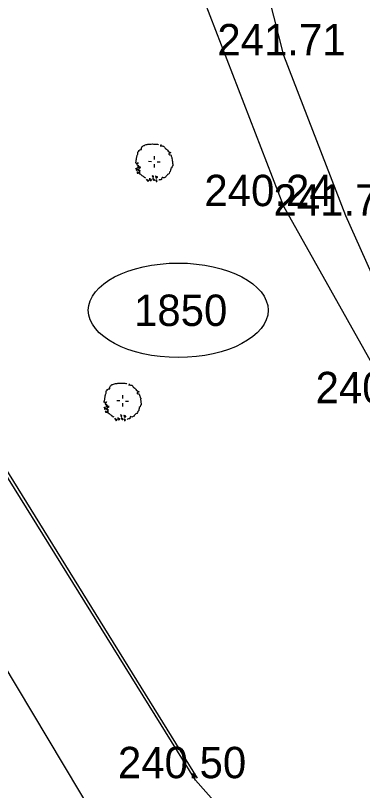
# Model space of a CAD drawing. Extents: x -601739 to -601440, y -1201912 to -1200862.
# Drawn here: x -601531.2 to -601509.07, y -1201685.45 to -1201636.06 of the extents above; entities that cross this region are included whole.
import ezdxf

# ---------------------------------------------------------------- set-up
doc = ezdxf.new("R2010")
doc.units = 0
for name, color, linetype in [('Hranice parcel', 7, 'Continuous'), ('Parcelní čísla', 7, 'Continuous'), ('u_dotčené parcely', 7, 'Continuous'), ('u_hrany', 7, 'Continuous'), ('u_vysadba', 7, 'Continuous'), ('u_vyska', 7, 'Continuous')]:
    doc.layers.add(name, color=color, linetype=linetype)

msp = doc.modelspace()

# ---------------------------------------------------------------- linework, layer by layer
at = {"layer": 'Hranice parcel'}
for points in [[(-601445.87, -1201723.83), (-601456.99, -1201723.59), (-601475.22, -1201720.69), (-601492.39, -1201715.61), (-601519.73, -1201684.8), (-601540.64, -1201651.14), (-601563.05, -1201608.38), (-601567.44, -1201599.25)], [(-601574.75, -1201602.78), (-601570.23, -1201611.8), (-601545.97, -1201654.03), (-601525.15, -1201688.8), (-601494.52, -1201722.78), (-601477.14, -1201727.24), (-601477.125, -1201727.243)]]:
    msp.add_lwpolyline(points, dxfattribs=at)
at = {"layer": 'u_dotčené parcely'}
msp.add_ellipse((-601520.821, -1201654.846), major_axis=(-5.732, 0), ratio=0.524694, dxfattribs=at)
at = {"layer": 'u_hrany'}
for points in [[(-601514.2, -1201569.51), (-601517.03, -1201570.93), (-601522.49, -1201584.67), (-601523.6, -1201596.8), (-601523.78, -1201607.28), (-601522.35, -1201622.38), (-601520.26, -1201632.29), (-601514.11, -1201648.21), (-601507.05, -1201660.77), (-601502.96, -1201664.86), (-601510.13, -1201648.82), (-601514.08, -1201638.6), (-601517, -1201627.14), (-601517.98, -1201618.06), (-601518.55, -1201594.5), (-601514.93, -1201583.59), (-601509.76, -1201580.82)], [(-601567.51, -1201596.21), (-601562.55, -1201607.8), (-601549.33, -1201634.79), (-601540.29, -1201651.32), (-601519.62, -1201684.67)]]:
    msp.add_lwpolyline(points, dxfattribs=at)
at = {"layer": 'u_vysadba'}
for points in [[(-601523.335, -1201644.685), (-601523.333, -1201644.656), (-601523.273, -1201644.63), (-601523.243, -1201644.617), (-601523.213, -1201644.604), (-601523.184, -1201644.605), (-601523.155, -1201644.607), (-601523.168, -1201644.577), (-601523.181, -1201644.547), (-601523.164, -1201644.504), (-601523.147, -1201644.461), (-601523.116, -1201644.418), (-601523.085, -1201644.391), (-601523.054, -1201644.363), (-601523.009, -1201644.336), (-601522.965, -1201644.338), (-601522.934, -1201644.311), (-601522.86, -1201644.285), (-601522.801, -1201644.274), (-601522.756, -1201644.262), (-601522.698, -1201644.265), (-601522.653, -1201644.252), (-601522.609, -1201644.255), (-601522.536, -1201644.259), (-601522.463, -1201644.248), (-601522.39, -1201644.252), (-601522.302, -1201644.256), (-601522.214, -1201644.261), (-601522.141, -1201644.265), (-601522.098, -1201644.282), (-601522.07, -1201644.298)], [(-601521.923, -1201644.291), (-601521.939, -1201644.319), (-601521.941, -1201644.349), (-601521.957, -1201644.377), (-601521.912, -1201644.365), (-601521.883, -1201644.366), (-601521.854, -1201644.368), (-601521.811, -1201644.385), (-601521.767, -1201644.387), (-601521.725, -1201644.419), (-601521.697, -1201644.449), (-601521.67, -1201644.495), (-601521.628, -1201644.526), (-601521.572, -1201644.573), (-601521.53, -1201644.619), (-601521.503, -1201644.65), (-601521.462, -1201644.711), (-601521.405, -1201644.743), (-601521.363, -1201644.775), (-601521.32, -1201644.791), (-601521.321, -1201644.821)], [(-601523.335, -1201644.685), (-601523.336, -1201644.7), (-601523.382, -1201644.741), (-601523.413, -1201644.769), (-601523.415, -1201644.813), (-601523.417, -1201644.856), (-601523.42, -1201644.915), (-601523.437, -1201644.958), (-601523.453, -1201644.986), (-601523.469, -1201645.015), (-601523.487, -1201645.072), (-601523.489, -1201645.102), (-601523.492, -1201645.16), (-601523.494, -1201645.204), (-601523.496, -1201645.233), (-601523.514, -1201645.305), (-601523.531, -1201645.348), (-601523.533, -1201645.392), (-601523.549, -1201645.42), (-601523.536, -1201645.45), (-601523.493, -1201645.467), (-601523.404, -1201645.443), (-601523.374, -1201645.43), (-601523.407, -1201645.487), (-601523.437, -1201645.514), (-601523.453, -1201645.543), (-601523.456, -1201645.586), (-601523.427, -1201645.588), (-601523.383, -1201645.59), (-601523.37, -1201645.62), (-601523.387, -1201645.663), (-601523.403, -1201645.692), (-601523.405, -1201645.736), (-601523.407, -1201645.779)], [(-601521.321, -1201644.821), (-601521.366, -1201644.833), (-601521.411, -1201644.845), (-601521.427, -1201644.874), (-601521.414, -1201644.904), (-601521.387, -1201644.949), (-601521.357, -1201644.936), (-601521.312, -1201644.924), (-601521.284, -1201644.954), (-601521.271, -1201644.984), (-601521.273, -1201645.014), (-601521.247, -1201645.074), (-601521.235, -1201645.118), (-601521.222, -1201645.163), (-601521.195, -1201645.208), (-601521.197, -1201645.237), (-601521.199, -1201645.281), (-601521.201, -1201645.31), (-601521.189, -1201645.355), (-601521.177, -1201645.414), (-601521.18, -1201645.472), (-601521.169, -1201645.532), (-601521.17, -1201645.561), (-601521.172, -1201645.59), (-601521.174, -1201645.634), (-601521.205, -1201645.661), (-601521.206, -1201645.691), (-601521.223, -1201645.734), (-601521.239, -1201645.762), (-601521.285, -1201645.804), (-601521.289, -1201645.862), (-601521.306, -1201645.92), (-601521.325, -1201645.992), (-601521.372, -1201646.048), (-601521.405, -1201646.119), (-601521.437, -1201646.176), (-601521.497, -1201646.202), (-601521.528, -1201646.23), (-601521.574, -1201646.272), (-601521.605, -1201646.314), (-601521.622, -1201646.357), (-601521.682, -1201646.383), (-601521.727, -1201646.395), (-601521.757, -1201646.408), (-601521.8, -1201646.391), (-601521.843, -1201646.375), (-601521.86, -1201646.418), (-601521.877, -1201646.475), (-601521.894, -1201646.518), (-601521.939, -1201646.531), (-601521.983, -1201646.528)], [(-601522.335, -1201645.227), (-601522.325, -1201645.022)], [(-601523.539, -1201645.772), (-601523.526, -1201645.802), (-601523.513, -1201645.847), (-601523.5, -1201645.877), (-601523.502, -1201645.906), (-601523.473, -1201645.922), (-601523.443, -1201645.895), (-601523.397, -1201645.853), (-601523.426, -1201645.852), (-601523.468, -1201645.82), (-601523.511, -1201645.803)], [(-601523.357, -1201645.65), (-601523.359, -1201645.694), (-601523.346, -1201645.724), (-601523.334, -1201645.769), (-601523.32, -1201645.799), (-601523.291, -1201645.8), (-601523.275, -1201645.772), (-601523.215, -1201645.746), (-601523.258, -1201645.729), (-601523.287, -1201645.713), (-601523.344, -1201645.68)], [(-601522.519, -1201645.378), (-601522.724, -1201645.367)], [(-601522.352, -1201645.533), (-601522.362, -1201645.738)], [(-601522.169, -1201645.396), (-601521.963, -1201645.393)], [(-601523.449, -1201646.011), (-601523.439, -1201646.1), (-601523.395, -1201646.102), (-601523.366, -1201646.104), (-601523.321, -1201646.091), (-601523.379, -1201646.074), (-601523.423, -1201646.071), (-601523.436, -1201646.041)], [(-601523.381, -1201645.839), (-601523.34, -1201645.885), (-601523.298, -1201645.932), (-601523.256, -1201645.963)], [(-601523.256, -1201645.963), (-601523.285, -1201645.962), (-601523.314, -1201645.96), (-601523.344, -1201645.958), (-601523.357, -1201645.929), (-601523.355, -1201645.899), (-601523.368, -1201645.869)], [(-601522.885, -1201646.422), (-601522.928, -1201646.405), (-601522.956, -1201646.389), (-601522.986, -1201646.387), (-601523.012, -1201646.342), (-601523.041, -1201646.326), (-601523.083, -1201646.294), (-601523.126, -1201646.277), (-601523.168, -1201646.231), (-601523.195, -1201646.201), (-601523.267, -1201646.168), (-601523.264, -1201646.124), (-601523.262, -1201646.08), (-601523.275, -1201646.05), (-601523.304, -1201646.034), (-601523.272, -1201645.992), (-601523.243, -1201645.993)], [(-601522.481, -1201646.253), (-601522.47, -1201646.327), (-601522.443, -1201646.372), (-601522.398, -1201646.36), (-601522.397, -1201646.331), (-601522.395, -1201646.301), (-601522.438, -1201646.285), (-601522.467, -1201646.268)], [(-601522.278, -1201646.293), (-601522.252, -1201646.353), (-601522.239, -1201646.398), (-601522.212, -1201646.428), (-601522.182, -1201646.415), (-601522.15, -1201646.373), (-601522.149, -1201646.344), (-601522.192, -1201646.341), (-601522.221, -1201646.325), (-601522.249, -1201646.309), (-601522.278, -1201646.308)], [(-601522.873, -1201646.481), (-601522.777, -1201646.603), (-601522.75, -1201646.649), (-601522.719, -1201646.606), (-601522.717, -1201646.577), (-601522.746, -1201646.561), (-601522.789, -1201646.544), (-601522.817, -1201646.528), (-601522.846, -1201646.512)], [(-601522.651, -1201646.434), (-601522.655, -1201646.507), (-601522.643, -1201646.552), (-601522.615, -1201646.583), (-601522.556, -1201646.571), (-601522.525, -1201646.543), (-601522.538, -1201646.514), (-601522.581, -1201646.497), (-601522.624, -1201646.48)], [(-601522.446, -1201646.431), (-601522.362, -1201646.508), (-601522.334, -1201646.524), (-601522.321, -1201646.554), (-601522.352, -1201646.582), (-601522.381, -1201646.58), (-601522.394, -1201646.55), (-601522.421, -1201646.505), (-601522.448, -1201646.474)], [(-601522.247, -1201646.544), (-601522.236, -1201646.617), (-601522.223, -1201646.647), (-601522.193, -1201646.634), (-601522.162, -1201646.592), (-601522.189, -1201646.561), (-601522.218, -1201646.545), (-601522.247, -1201646.544)], [(-601521.983, -1201646.528), (-601522.027, -1201646.541), (-601522.058, -1201646.568)], [(-601525.353, -1201659.926), (-601525.352, -1201659.897), (-601525.292, -1201659.871), (-601525.262, -1201659.858), (-601525.232, -1201659.845), (-601525.203, -1201659.847), (-601525.173, -1201659.848), (-601525.186, -1201659.818), (-601525.199, -1201659.788), (-601525.183, -1201659.745), (-601525.166, -1201659.702), (-601525.134, -1201659.66), (-601525.103, -1201659.632), (-601525.073, -1201659.605), (-601525.027, -1201659.578), (-601524.983, -1201659.58), (-601524.953, -1201659.552), (-601524.878, -1201659.527), (-601524.819, -1201659.515), (-601524.774, -1201659.503), (-601524.716, -1201659.506), (-601524.671, -1201659.494), (-601524.628, -1201659.496), (-601524.555, -1201659.5), (-601524.481, -1201659.489), (-601524.408, -1201659.493), (-601524.32, -1201659.498), (-601524.233, -1201659.502), (-601524.16, -1201659.506), (-601524.117, -1201659.523), (-601524.088, -1201659.539)], [(-601523.941, -1201659.532), (-601523.957, -1201659.561), (-601523.959, -1201659.59), (-601523.975, -1201659.619), (-601523.931, -1201659.606), (-601523.901, -1201659.608), (-601523.872, -1201659.609), (-601523.829, -1201659.626), (-601523.785, -1201659.629), (-601523.743, -1201659.66), (-601523.715, -1201659.691), (-601523.688, -1201659.736), (-601523.646, -1201659.768), (-601523.59, -1201659.815), (-601523.549, -1201659.861), (-601523.521, -1201659.891), (-601523.48, -1201659.952), (-601523.423, -1201659.984), (-601523.381, -1201660.016), (-601523.338, -1201660.033), (-601523.34, -1201660.062)], [(-601525.353, -1201659.926), (-601525.354, -1201659.941), (-601525.4, -1201659.983), (-601525.431, -1201660.01), (-601525.433, -1201660.054), (-601525.435, -1201660.098), (-601525.439, -1201660.156), (-601525.455, -1201660.199), (-601525.472, -1201660.228), (-601525.488, -1201660.256), (-601525.505, -1201660.314), (-601525.507, -1201660.343), (-601525.51, -1201660.401), (-601525.512, -1201660.445), (-601525.514, -1201660.474), (-601525.532, -1201660.547), (-601525.549, -1201660.59), (-601525.552, -1201660.633), (-601525.568, -1201660.662), (-601525.555, -1201660.692), (-601525.512, -1201660.709), (-601525.422, -1201660.684), (-601525.393, -1201660.671), (-601525.425, -1201660.728), (-601525.456, -1201660.756), (-601525.472, -1201660.784), (-601525.474, -1201660.828), (-601525.445, -1201660.829), (-601525.401, -1201660.832), (-601525.388, -1201660.862), (-601525.405, -1201660.905), (-601525.421, -1201660.933), (-601525.423, -1201660.977), (-601525.426, -1201661.021)], [(-601523.34, -1201660.062), (-601523.384, -1201660.074), (-601523.429, -1201660.087), (-601523.445, -1201660.115), (-601523.432, -1201660.145), (-601523.405, -1201660.19), (-601523.375, -1201660.177), (-601523.33, -1201660.165), (-601523.303, -1201660.196), (-601523.29, -1201660.226), (-601523.291, -1201660.255), (-601523.265, -1201660.315), (-601523.253, -1201660.36), (-601523.241, -1201660.404), (-601523.214, -1201660.449), (-601523.215, -1201660.479), (-601523.218, -1201660.522), (-601523.219, -1201660.552), (-601523.207, -1201660.596), (-601523.195, -1201660.655), (-601523.198, -1201660.714), (-601523.187, -1201660.773), (-601523.188, -1201660.802), (-601523.19, -1201660.831), (-601523.192, -1201660.875), (-601523.223, -1201660.903), (-601523.225, -1201660.932), (-601523.241, -1201660.975), (-601523.258, -1201661.004), (-601523.304, -1201661.045), (-601523.307, -1201661.103), (-601523.324, -1201661.161), (-601523.343, -1201661.233), (-601523.39, -1201661.289), (-601523.423, -1201661.361), (-601523.455, -1201661.418), (-601523.515, -1201661.444), (-601523.546, -1201661.472), (-601523.592, -1201661.513), (-601523.624, -1201661.555), (-601523.64, -1201661.598), (-601523.7, -1201661.624), (-601523.745, -1201661.637), (-601523.775, -1201661.65), (-601523.818, -1201661.633), (-601523.861, -1201661.616), (-601523.878, -1201661.659), (-601523.896, -1201661.717), (-601523.913, -1201661.76), (-601523.957, -1201661.772), (-601524.001, -1201661.77)], [(-601524.537, -1201660.619), (-601524.742, -1201660.609)], [(-601524.354, -1201660.468), (-601524.343, -1201660.264)], [(-601524.187, -1201660.638), (-601523.982, -1201660.634)], [(-601525.557, -1201661.014), (-601525.544, -1201661.044), (-601525.532, -1201661.088), (-601525.519, -1201661.118), (-601525.52, -1201661.148), (-601525.492, -1201661.164), (-601525.461, -1201661.136), (-601525.415, -1201661.095), (-601525.444, -1201661.093), (-601525.486, -1201661.062), (-601525.529, -1201661.045)], [(-601525.4, -1201661.081), (-601525.358, -1201661.127), (-601525.317, -1201661.173), (-601525.274, -1201661.205)], [(-601525.274, -1201661.205), (-601525.303, -1201661.203), (-601525.333, -1201661.201), (-601525.362, -1201661.2), (-601525.375, -1201661.17), (-601525.373, -1201661.141), (-601525.386, -1201661.111)], [(-601525.375, -1201660.892), (-601525.377, -1201660.936), (-601525.364, -1201660.966), (-601525.352, -1201661.01), (-601525.339, -1201661.04), (-601525.31, -1201661.042), (-601525.293, -1201661.013), (-601525.233, -1201660.987), (-601525.277, -1201660.97), (-601525.305, -1201660.954), (-601525.362, -1201660.922)], [(-601524.37, -1201660.775), (-601524.381, -1201660.979)], [(-601525.467, -1201661.253), (-601525.457, -1201661.341), (-601525.413, -1201661.344), (-601525.384, -1201661.345), (-601525.34, -1201661.333), (-601525.397, -1201661.315), (-601525.441, -1201661.313), (-601525.454, -1201661.283)], [(-601524.903, -1201661.663), (-601524.946, -1201661.647), (-601524.975, -1201661.63), (-601525.004, -1201661.629), (-601525.031, -1201661.583), (-601525.059, -1201661.567), (-601525.101, -1201661.536), (-601525.144, -1201661.519), (-601525.186, -1201661.473), (-601525.214, -1201661.442), (-601525.285, -1201661.409), (-601525.283, -1201661.365), (-601525.28, -1201661.321), (-601525.293, -1201661.291), (-601525.322, -1201661.275), (-601525.29, -1201661.233), (-601525.261, -1201661.235)], [(-601524.499, -1201661.494), (-601524.488, -1201661.568), (-601524.461, -1201661.614), (-601524.417, -1201661.601), (-601524.415, -1201661.572), (-601524.414, -1201661.543), (-601524.457, -1201661.526), (-601524.485, -1201661.51)], [(-601524.296, -1201661.534), (-601524.27, -1201661.594), (-601524.258, -1201661.639), (-601524.23, -1201661.67), (-601524.2, -1201661.657), (-601524.168, -1201661.614), (-601524.167, -1201661.585), (-601524.211, -1201661.583), (-601524.239, -1201661.567), (-601524.268, -1201661.551), (-601524.297, -1201661.549)], [(-601524.892, -1201661.723), (-601524.796, -1201661.845), (-601524.769, -1201661.89), (-601524.737, -1201661.848), (-601524.736, -1201661.819), (-601524.764, -1201661.803), (-601524.807, -1201661.786), (-601524.836, -1201661.769), (-601524.864, -1201661.753)], [(-601524.67, -1201661.676), (-601524.673, -1201661.749), (-601524.661, -1201661.793), (-601524.633, -1201661.824), (-601524.574, -1201661.813), (-601524.544, -1201661.785), (-601524.557, -1201661.755), (-601524.6, -1201661.738), (-601524.643, -1201661.721)], [(-601524.464, -1201661.672), (-601524.381, -1201661.75), (-601524.352, -1201661.766), (-601524.339, -1201661.796), (-601524.37, -1201661.823), (-601524.399, -1201661.822), (-601524.412, -1201661.792), (-601524.439, -1201661.747), (-601524.467, -1201661.716)], [(-601524.265, -1201661.785), (-601524.255, -1201661.859), (-601524.241, -1201661.889), (-601524.212, -1201661.876), (-601524.18, -1201661.833), (-601524.208, -1201661.803), (-601524.236, -1201661.787), (-601524.265, -1201661.785)], [(-601524.001, -1201661.77), (-601524.046, -1201661.782), (-601524.076, -1201661.81)]]:
    msp.add_lwpolyline(points, dxfattribs=at)

# ---------------------------------------------------------------- texts
at = {"layer": 'Parcelní čísla'}
msp.add_text('1850', height=2, dxfattribs=at).set_placement((-601523.64, -1201655.846))
at = {"layer": 'u_vyska'}
for s, p in [('241.71', (-601518.328, -1201638.6)), ('240.24', (-601519.153, -1201648.21)), ('241.75', (-601514.748, -1201648.82)), ('240.88', (-601512.065, -1201660.77)), ('240.50', (-601524.665, -1201684.67))]:
    msp.add_text(s, height=2, dxfattribs=at).set_placement(p)

doc.saveas('drawing.dxf')
